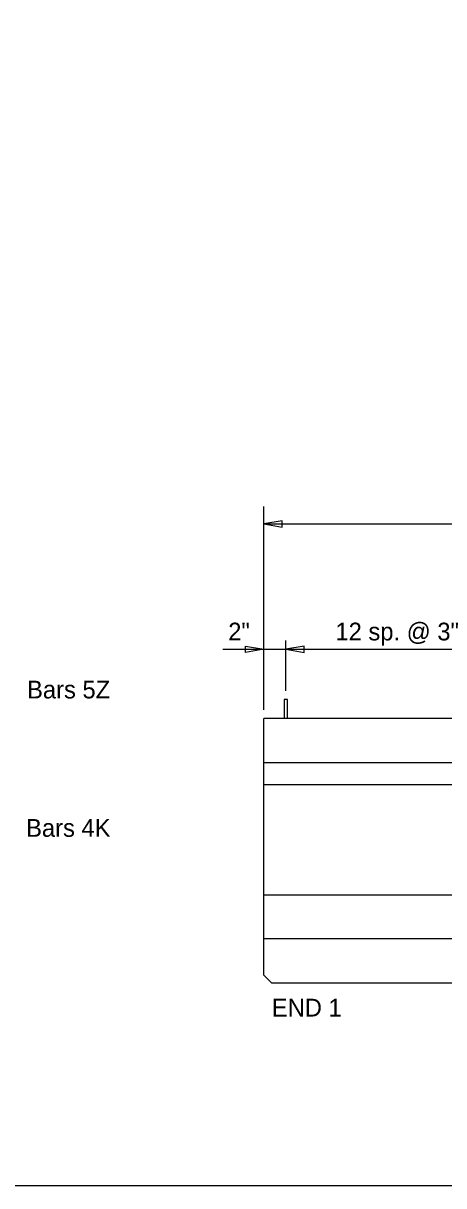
# Model space of a CAD drawing. Extents: x 0 to 34.7, y -1.1 to 13.9.
# Drawn here: x 4.47 to 6.86, y 0 to 6.6 of the extents above; entities that cross this region are included whole.
import ezdxf

# ---------------------------------------------------------------- set-up
doc = ezdxf.new("R2010")
doc.units = 0
for name, color, linetype in [('ActivePts-ConstElements', 7, 'Continuous'), ('BeamConc', 7, 'Continuous'), ('Rebar', 7, 'Continuous'), ('SheetLines_dp', 7, 'Continuous'), ('TextStructures', 7, 'Continuous')]:
    doc.layers.add(name, color=color, linetype=linetype)

msp = doc.modelspace()

# ---------------------------------------------------------------- linework, layer by layer
at = {"layer": 'ActivePts-ConstElements'}
msp.add_lwpolyline([(0, 13.2), (20.5333, 13.2), (20.5333, 0), (0, 0)], close=True, dxfattribs=at)
at = {"layer": 'BeamConc'}
for p, q in [((5.841, 1.1949), (5.841, 2.6522)), ((17.1544, 2.6523), (5.8411, 2.6523)), ((5.8411, 2.4023), (17.1544, 2.4023)), ((5.8411, 2.2773), (17.1544, 2.2773)), ((5.8411, 1.6522), (17.1544, 1.6522)), ((17.1544, 1.4022), (5.8411, 1.4022)), ((5.841, 1.1949), (5.8837, 1.1522)), ((5.8837, 1.1522), (17.1544, 1.1522))]:
    msp.add_line(p, q, dxfattribs=at)
at = {"layer": 'Rebar'}
for p, q in [((5.9747, 2.7598), (5.9574, 2.7598)), ((5.9574, 2.7598), (5.9574, 2.6523)), ((5.9747, 2.6523), (5.9747, 2.7598))]:
    msp.add_line(p, q, dxfattribs=at)
at = {"layer": 'SheetLines_dp'}
for p, q in [((5.841, 2.7027), (5.841, 3.8565)), ((5.6086, 3.0459), (17.4695, 3.0459)), ((5.9661, 2.8101), (5.9661, 3.0962))]:
    msp.add_line(p, q, dxfattribs=at)
msp.add_lwpolyline([(5.841, 3.7574), (17.178, 3.7574), (17.178, 3.8091), (17.2005, 3.7574), (17.223, 3.7058), (17.223, 3.7574), (20.0086, 3.7574)], dxfattribs=at)
for points in [[(5.841, 3.7574), (5.9452, 3.7398), (5.9452, 3.7751)], [(5.841, 3.0459), (5.7369, 3.0282), (5.7369, 3.0635)], [(5.9661, 3.0459), (6.0702, 3.0282), (6.0702, 3.0635)]]:
    msp.add_lwpolyline(points, close=True, dxfattribs=at)

# ---------------------------------------------------------------- texts
at = {"layer": 'TextStructures'}
for s, p in [('2"', (5.6387, 3.0961)), ('12 sp. @ 3" ', (6.2479, 3.0961)), ('Bars 5Z', (4.4959, 2.7667)), ('Bars 4K', (4.4904, 1.9812)), ('END 1', (5.8865, 0.9609))]:
    msp.add_text(s, height=0.1008, dxfattribs=at).set_placement(p)

doc.saveas('drawing.dxf')
